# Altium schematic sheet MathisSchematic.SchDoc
size A4; SheetNumber: 1; SheetTotal: 1
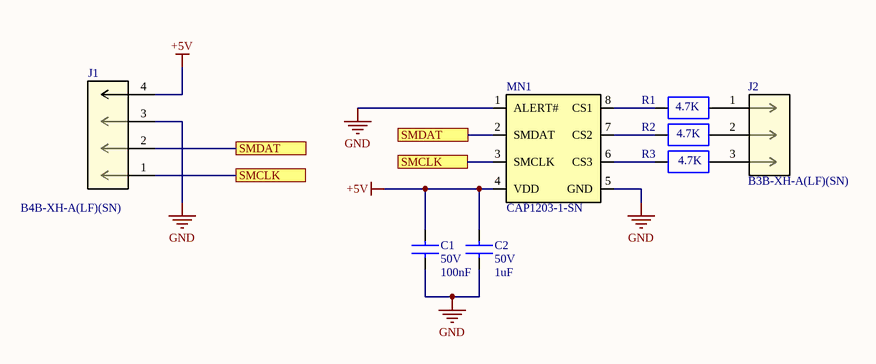
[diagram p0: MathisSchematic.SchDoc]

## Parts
C1  value 100nF  Voltage Rating (DC): 50V  [CAP_0805]  (hidden comment: MCU0805R104KCT)
C2  value 1uF  Voltage Rating (DC): 50V  [CAP_0805]  (hidden comment: GRM21BR71H105KA12L)
J1  B4B-XH-A(LF)(SN)  [B4B-XH-A]
J2  B3B-XH-A(LF)(SN)  [B3B-XH-A]
MN1  CAP1203-1-SN  [FP-C04-057-SN-IPC_B]
R1  Resistance: 4.7K  [RES_0805]  (hidden comment: CRCW08054K70FKEA)
R2  Resistance: 4.7K  [RES_0805]  (hidden comment: CRCW08054K70FKEA)
R3  Resistance: 4.7K  [RES_0805]  (hidden comment: CRCW08054K70FKEA)

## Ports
SMCLK, SMDAT

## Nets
+5V: C1.2 C2.2 J1.4 MN1.4(VDD)
GND: C1.1 C2.1 J1.3 MN1.1(ALERT#) MN1.5(GND)
SMCLK: J1.1 MN1.3(SMCLK) ; port SMCLK
SMDAT: J1.2 MN1.2(SMDAT) ; port SMDAT
NetJ2_1: J2.1 R1.2
NetJ2_2: J2.2 R2.2
NetJ2_3: J2.3 R3.1
NetMN1_6: MN1.6(CS3) R3.2
NetMN1_7: MN1.7(CS2) R2.1
NetMN1_8: MN1.8(CS1) R1.1

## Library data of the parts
C1 = U0805R104KCT-1: Cap Ceramic 0.1uF 50V X7R ±10% SMD 0805 125°C T/R; Sylob: 71023821
C2 = GRM21BR71H105KA12L-1: 0805 1 uF 50 V ±10% Tolerance X7R Multilayer Ceramic Chip Capacitor; Sylob: 71026759
J1 = CMP-047-000046-2: JST Connector Header, XH Series, 4 Positions, 2.5mm Pitch Through Hole Crimp Top Entry Shrouded Header; Max Voltage Rating (AC): 250V; Max Current Rating: 3A; Number of Positions: 4; Sylob: 71041699; Gender: Male; Contact Resistance: 20mR; Mated Stacking Heights: 9.8mm; Insulation Resistance: 1GR; Wire/Cable Gauge: 22AWG
J2 = CMP-047-000044-2: JST Connector Header, XH Series, 3 Positions, 2.50mm, Through Hole, Press-Fit, Solder, Natural; Sylob: 71041700
MN1 = CMP-000015-1: Touch Sensor Capacitive 3 Key 3V to 5.5V SMD 8-Pin SOIC Tube; Number of Inputs: 3; Interface: I2C,SMBus; Operating Supply Current: 750uA; Resolution: 8b
R1-R3 = CMP-079-000100-3: Resistor Thick Film 0805 4.7K Ohm 1% ±100ppm/°C Molded SMD SMD Paper T/R; Sylob: 71021825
